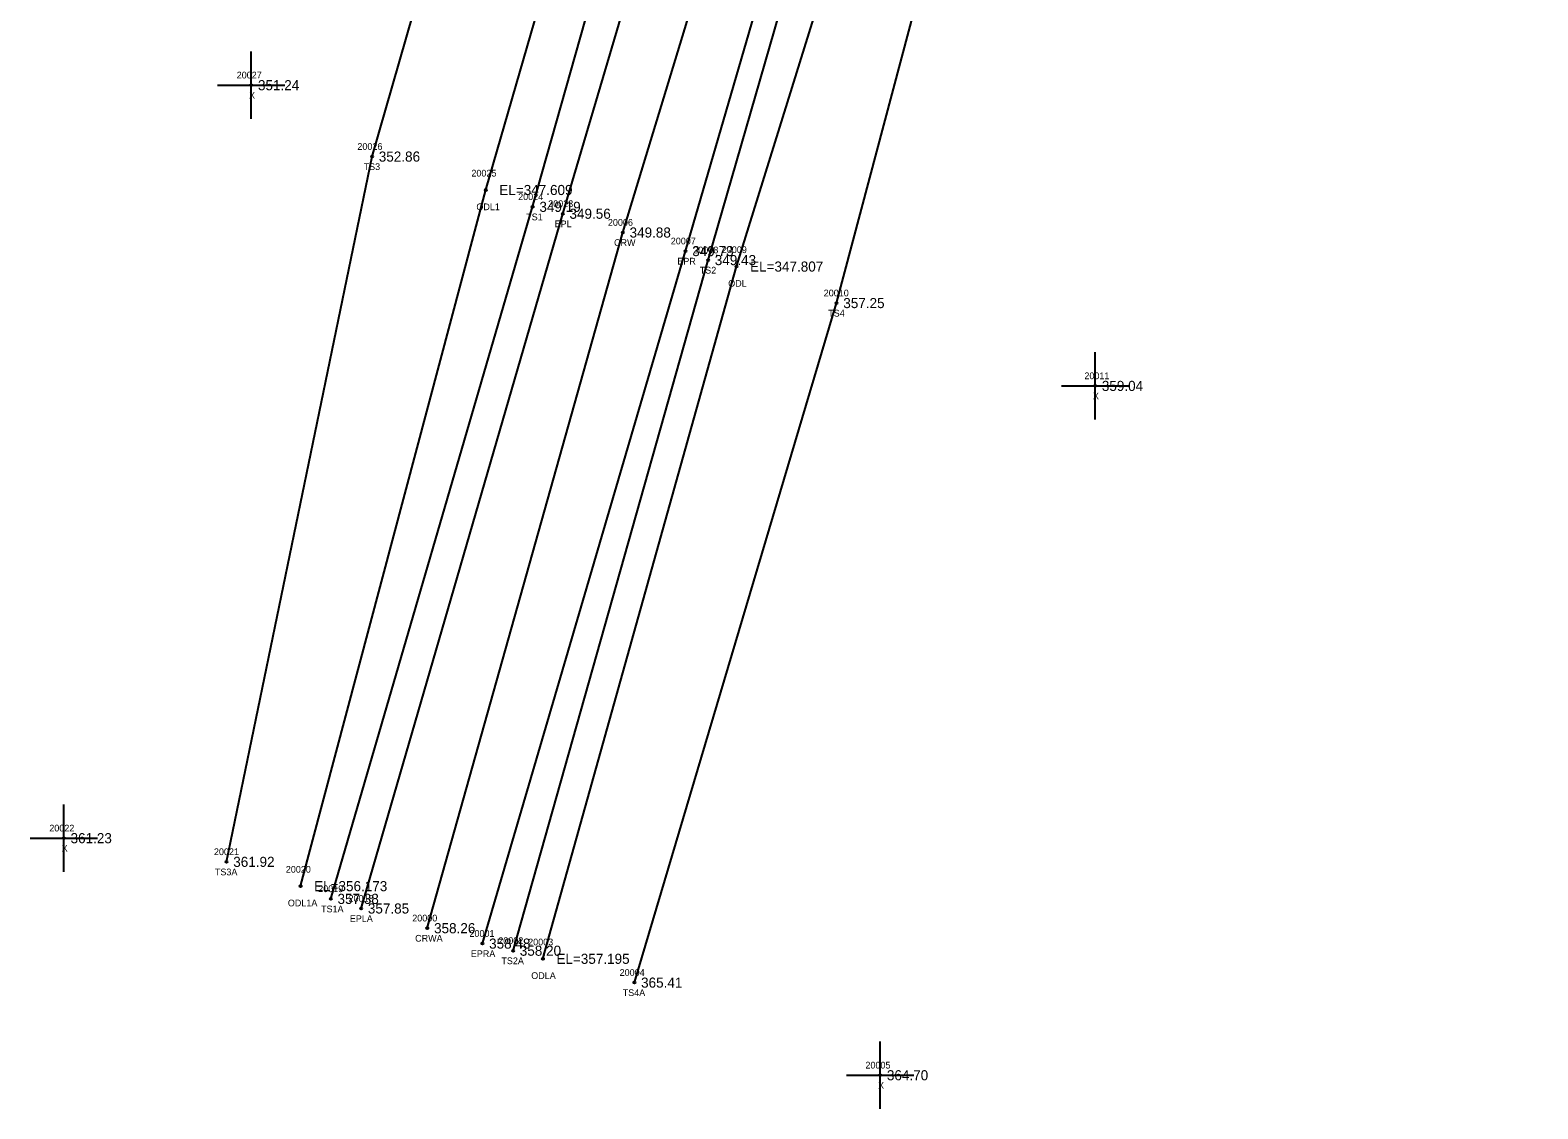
# Model space of a CAD drawing. Extents: x 2231109 to 2232328, y 1035718 to 1036919.
# Drawn here: x 2231109.2 to 2231333.2, y 1035718.3 to 1035878.7 of the extents above; entities that cross this region are included whole.
import ezdxf

# ---------------------------------------------------------------- set-up
doc = ezdxf.new("R2010")
doc.units = 0
for name, color, linetype in [('RD_DTM_BkLn1', 7, 'Continuous'), ('RD_DTM_BkLn2', 7, 'Continuous'), ('RD_DTM_BkLn_txCode', 7, 'Continuous'), ('RD_EX_H2O', 7, 'Continuous'), ('RD_EX_H2O_txCode', 7, 'Continuous'), ('RD_EX_Misc', 7, 'Continuous'), ('RD_EX_Misc_txCode', 7, 'Continuous'), ('RD_EX_Road', 7, 'Continuous'), ('RD_EX_Road_txCode', 7, 'Continuous'), ('RD_EX_TX_H2O_ELEV', 7, 'Continuous'), ('RD_EX_TX_Misc_ELEV', 7, 'Continuous'), ('RD_EX_TX_Road_ELEV', 7, 'Continuous'), ('RD_HC_Survey_ELEV', 7, 'Continuous'), ('RD_HC_Survey_txCode', 7, 'Continuous'), ('RD_SMD_Locator', 7, 'Continuous')]:
    doc.layers.add(name, color=color, linetype=linetype)

msp = doc.modelspace()

# ---------------------------------------------------------------- linework, layer by layer
at = {"layer": 'RD_DTM_BkLn1'}
msp.add_lwpolyline([(2231168.25, 1035745.18), (2231197.3, 1035848.59), (2231226.32, 1035944.04), (2231254.24, 1036037.31), (2231285.91, 1036129.66), (2231306.91, 1036176.17), (2231330.56, 1036216.58), (2231356.95, 1036257.36), (2231387.54, 1036294.26), (2231422.35, 1036330.42), (2231422.35, 1036330.4), (2231458.4, 1036362.33), (2231503.71, 1036399.67), (2231541.46, 1036424.96)], dxfattribs=at)
at = {"layer": 'RD_DTM_BkLn2'}
for points in [[(2231153.91, 1035749.54), (2231183.9, 1035852.41), (2231210.94, 1035948.08), (2231242.08, 1036041.75), (2231274.33, 1036134.79), (2231295.17, 1036181.88), (2231317.55, 1036225.12), (2231346.22, 1036265.16), (2231373.72, 1036304.6), (2231409.94, 1036342.78), (2231447.25, 1036376.56), (2231493.69, 1036413.26), (2231528.08, 1036438.61), (2231532.84, 1036438.24), (2231534.71, 1036436.33)], [(2231180.99, 1035741.83), (2231209.96, 1035844.49), (2231237.45, 1035939.8), (2231265.71, 1036032.03), (2231300.77, 1036123.1), (2231321.14, 1036169.41), (2231342.59, 1036208.04), (2231368.53, 1036247.79), (2231397.69, 1036285.75), (2231431.64, 1036319.41), (2231468.01, 1036352.78), (2231515.06, 1036385.58), (2231547.14, 1036404.2), (2231548.89, 1036408.2), (2231548.45, 1036412.54)], [(2231138.42, 1035755.04), (2231160.04, 1035859.88), (2231169.24, 1035891.81), (2231170.96, 1035897.04), (2231186.09, 1035952.96), (2231232.07, 1036044.88), (2231264.05, 1036138.89), (2231281.88, 1036181.64), (2231289.28, 1036185.01)], [(2231199.01, 1035737.09), (2231229.05, 1035838.1), (2231254.27, 1035932.98), (2231277.77, 1036019.92), (2231276.31, 1036031.77)]]:
    msp.add_lwpolyline(points, dxfattribs=at)
at = {"layer": 'RD_EX_H2O'}
for points in [[(2231149.43, 1035751.43), (2231176.95, 1035854.91), (2231204.32, 1035949.66), (2231235.24, 1036043.84), (2231268.21, 1036137.52), (2231289.28, 1036185.01)], [(2231185.43, 1035740.63), (2231214.2, 1035843.53), (2231243.37, 1035937.44), (2231276.31, 1036031.77)]]:
    msp.add_lwpolyline(points, dxfattribs=at)
at = {"layer": 'RD_EX_Misc'}
for p, q in [((2231142.09, 1035865.49), (2231142.09, 1035875.49)), ((2231137.09, 1035870.49), (2231147.09, 1035870.49)), ((2231267.46, 1035820.79), (2231267.46, 1035830.79)), ((2231262.46, 1035825.79), (2231272.46, 1035825.79)), ((2231114.25, 1035753.56), (2231114.25, 1035763.56)), ((2231109.25, 1035758.56), (2231119.25, 1035758.56)), ((2231235.53, 1035718.32), (2231235.53, 1035728.32)), ((2231230.53, 1035723.32), (2231240.53, 1035723.32))]:
    msp.add_line(p, q, dxfattribs=at)
at = {"layer": 'RD_EX_Road'}
for points in [[(2231158.42, 1035748.11), (2231188.37, 1035851.38), (2231216.59, 1035946.92), (2231244.77, 1036040.72), (2231278.59, 1036133.31), (2231299.55, 1036179.73), (2231323.11, 1036221.2), (2231350.7, 1036262.3), (2231381.59, 1036299.29), (2231415.97, 1036336.9), (2231452.94, 1036369.74), (2231498.19, 1036405.3), (2231537.2, 1036432.57), (2231541.46, 1036424.96)], [(2231176.43, 1035742.89), (2231206.61, 1035845.83), (2231234.19, 1035940.65), (2231261.92, 1036033.75), (2231294.68, 1036125.28), (2231316.11, 1036171.75), (2231338.19, 1036211.09), (2231363.83, 1036252.38), (2231394.08, 1036289.28), (2231427.67, 1036324.2), (2231464.37, 1036355.5), (2231508.96, 1036392.41), (2231546.55, 1036416.22), (2231541.46, 1036424.96)]]:
    msp.add_lwpolyline(points, dxfattribs=at)
at = {"layer": 'RD_SMD_Locator'}
for centre in [(2231142.09, 1035870.49), (2231160.04, 1035859.88), (2231176.95, 1035854.91), (2231183.9, 1035852.41), (2231188.37, 1035851.38), (2231197.3, 1035848.59), (2231206.61, 1035845.83), (2231209.96, 1035844.49), (2231214.2, 1035843.53), (2231229.05, 1035838.1), (2231267.46, 1035825.79), (2231114.25, 1035758.56), (2231138.42, 1035755.04), (2231149.43, 1035751.43), (2231153.91, 1035749.54), (2231158.42, 1035748.11), (2231168.25, 1035745.18), (2231176.43, 1035742.89), (2231180.99, 1035741.83), (2231185.43, 1035740.63), (2231199.01, 1035737.09), (2231235.53, 1035723.32)]:
    msp.add_circle(centre, 0.15, dxfattribs=at)

# ---------------------------------------------------------------- texts
at = {"layer": 'RD_DTM_BkLn_txCode'}
for s, p in [('20026', (2231157.86, 1035860.88)), ('TS3', (2231158.79, 1035857.88)), ('20024', (2231181.75, 1035853.41)), ('TS1', (2231182.94, 1035850.41)), ('20008', (2231207.76, 1035845.49)), ('TS2', (2231208.72, 1035842.49)), ('20010', (2231227.14, 1035839.1)), ('TS4', (2231227.81, 1035836.1)), ('20021', (2231136.55, 1035756.04)), ('TS3A', (2231136.69, 1035753.04)), ('20019', (2231152.04, 1035750.54)), ('TS1A', (2231152.46, 1035747.54)), ('20002', (2231178.79, 1035742.83)), ('TS2A', (2231179.25, 1035739.83)), ('20004', (2231196.82, 1035738.09)), ('TS4A', (2231197.28, 1035735.09))]:
    msp.add_text(s, height=1, dxfattribs=at).set_placement(p)
at = {"layer": 'RD_EX_H2O_txCode'}
for s, p in [('20025', (2231174.8, 1035856.91)), ('ODL1', (2231175.54, 1035851.91)), ('20009', (2231212, 1035845.53)), ('ODL', (2231212.95, 1035840.53)), ('20020', (2231147.23, 1035753.43)), ('ODL1A', (2231147.53, 1035748.43)), ('20003', (2231183.23, 1035742.63)), ('ODLA', (2231183.69, 1035737.63))]:
    msp.add_text(s, height=1, dxfattribs=at).set_placement(p)
at = {"layer": 'RD_EX_Misc_txCode'}
for s, p in [('20027', (2231139.93, 1035871.49)), ('X', (2231141.77, 1035868.49)), ('20011', (2231265.87, 1035826.79)), ('X', (2231267.14, 1035823.79)), ('20022', (2231112.09, 1035759.56)), ('X', (2231113.93, 1035756.56)), ('20005', (2231233.34, 1035724.32)), ('X', (2231235.22, 1035721.32))]:
    msp.add_text(s, height=1, dxfattribs=at).set_placement(p)
at = {"layer": 'RD_EX_Road_txCode'}
for s, p in [('20023', (2231186.21, 1035852.38)), ('EPL', (2231187.16, 1035849.38)), ('20007', (2231204.42, 1035846.83)), ('EPR', (2231205.39, 1035843.83)), ('20018', (2231156.55, 1035749.11)), ('EPLA', (2231156.73, 1035746.11)), ('20001', (2231174.51, 1035743.89)), ('EPRA', (2231174.71, 1035740.89))]:
    msp.add_text(s, height=1, dxfattribs=at).set_placement(p)
at = {"layer": 'RD_EX_TX_H2O_ELEV'}
for s, p in [('EL=347.609', (2231178.95, 1035854.16)), ('EL=347.807', (2231216.2, 1035842.78)), ('EL=356.173', (2231151.43, 1035750.68)), ('EL=357.195', (2231187.43, 1035739.88))]:
    msp.add_text(s, height=1.5, dxfattribs=at).set_placement(p)
at = {"layer": 'RD_EX_TX_Misc_ELEV'}
for s, p in [('351.24', (2231143.09, 1035869.74)), ('352.86', (2231161.04, 1035859.13)), ('349.19', (2231184.9, 1035851.66)), ('349.43', (2231210.96, 1035843.74)), ('357.25', (2231230.05, 1035837.35)), ('359.04', (2231268.46, 1035825.04)), ('361.23', (2231115.25, 1035757.81)), ('361.92', (2231139.42, 1035754.29)), ('357.38', (2231154.91, 1035748.79)), ('358.20', (2231181.99, 1035741.08)), ('365.41', (2231200.01, 1035736.34)), ('364.70', (2231236.53, 1035722.57))]:
    msp.add_text(s, height=1.5, dxfattribs=at).set_placement(p)
at = {"layer": 'RD_EX_TX_Road_ELEV'}
for s, p in [('349.56', (2231189.37, 1035850.63)), ('349.73', (2231207.61, 1035845.08)), ('357.85', (2231159.42, 1035747.36)), ('358.48', (2231177.43, 1035742.14))]:
    msp.add_text(s, height=1.5, dxfattribs=at).set_placement(p)
at = {"layer": 'RD_HC_Survey_ELEV'}
for s, p in [('349.88', (2231198.3, 1035847.84)), ('358.26', (2231169.25, 1035744.43))]:
    msp.add_text(s, height=1.5, dxfattribs=at).set_placement(p)
at = {"layer": 'RD_HC_Survey_txCode'}
for s, p in [('20006', (2231195.08, 1035849.59)), ('CRW', (2231195.99, 1035846.59)), ('20000', (2231166.01, 1035746.18)), ('CRWA', (2231166.44, 1035743.18))]:
    msp.add_text(s, height=1, dxfattribs=at).set_placement(p)

doc.saveas('drawing.dxf')
